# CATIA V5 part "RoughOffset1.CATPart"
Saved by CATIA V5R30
Part number: Part2
Bounding box of the stored display mesh (mm): x -142.587 to 50, y -60 to 170, z -56 to 80
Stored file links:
  D:\PROJECTS\CATIA V56R 2020\Resources\Parts File\c17_catia_v6_6r2020_prt\RoughOffset1.CATPart
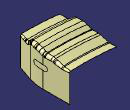
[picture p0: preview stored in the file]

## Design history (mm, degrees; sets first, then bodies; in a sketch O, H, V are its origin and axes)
Set1
  DatumSurface1
  DatumSurface2
  Sketch1 on xy-plane, origin (0, 0, 0), H (1, 0, 0), V (0, 1, 0)
    line L1 (180, 0) -> (420, 0)
    point P1 (180, 0)
    coincidence: P1 H
    horizontal: L1 H
  Point1: type OnPlane, Support xy-plane, H 200, V 5, Direction (1, 0, 0)
  Point2: type OnPlane, Support xy-plane, H 250, V 10, Direction (1, 0, 0)
  Point3: type OnPlane, Support xy-plane, H 320, V 13, Direction (1, 0, 0)
  Point4: type OnPlane, Support xy-plane, H 380, V 6, Direction (1, 0, 0)
  Point5: type OnPlane, Support xy-plane, H 400, V 5, Direction (1, 0, 0)
  LineCorner1: Elements (Point1; {linecornerpoint Pt Point2, Radius 60}; {linecornerpoint Pt Point3, Radius 55}; {linecornerpoint Pt Point4, Radius 80}; Point5)
  LawDistProj1: Reference Sketch1, Definition LineCorner1
  Intersect1: ToIntersect1 DatumSurface1, ToIntersect2 DatumSurface2
  CurvePar1: Length LawDistProj1, Offset Intersect1, Support DatumSurface1
  Point6: type OnCurve, Support Intersect1, Length 0
  Point7: type OnCurve, Support Intersect1, Length 48.6659 {= length(Intersect1) / 5}
  Point8: type OnCurve, Support Intersect1, Length 97.3318 {= (length(Intersect1)) * 2 / 5}
  Point9: type OnCurve, Support Intersect1, Length 145.9977 {= (length(Intersect1)) * 3 / 5}
  Point10: type OnCurve, Support Intersect1, Length 194.6636 {= (length(Intersect1)) * 4 / 5}
  Point11: type OnCurve, Support Intersect1, Length 243.3295 {= length(Intersect1)}
  Curve1: Elements (Point11; Point10; Point9; Point8; Point7; Point6)
  Fillet1: type BiTangent, Element1 DatumSurface2, Element2 DatumSurface1, Radius 25, Spine Curve1, HoldCurve CurvePar1
  Boundary1: Boundary Fillet1
  Split1: ToCut DatumSurface1, Cutting Boundary1
  Split2: ToCut DatumSurface2, Cutting Boundary1
  Join1: Elements (Split2; Fillet1; Split1)
  Offset1: Offset DatumSurface1, Length 20
  Offset2: Offset DatumSurface2, Length 20
  Trim1: Element1 Offset2, Element2 Offset1
  Fill1: Boundary ({fillboundary BoundaryWire edge of DatumSurface2, Support Join1}; {fillboundary BoundaryWire edge of DatumSurface2, Support Join1})
  Join2: Elements (Fill1; Join1)
Body1 (main body)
